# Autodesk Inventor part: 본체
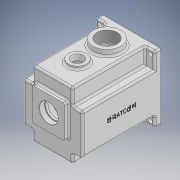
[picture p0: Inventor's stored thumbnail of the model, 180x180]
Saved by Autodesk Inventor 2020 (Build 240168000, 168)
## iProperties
Created: 2022-01
Part Number: 본체
Material: 일반
Document SubType Name: Modeling
Designer: user
Density: 1 g/cm^3
Appearance: 기본값
Mass: 519.717 g
Surface Area: 1171.01 cm^2
Volume: 519.717 cm^3
Author: user
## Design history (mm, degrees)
sketch "스케치1"
  geometry: L1 (-49, -55)-(49, -55); L2 (49, -55)-(49, 55); L3 (49, 55)-(-49, 55); L4 (-49, 55)-(-49, -55); L5 (-49, -55)-(49, 55); L6 (49, -55)-(-49, 55); 1 further point
  constraints: 12 end point, 2 midpoint, 2 parallel, 1 horizontal, 1 perpendicular
  dimensions: "d0" = 98 distance of L3.end L2.end; "d1" = 110 distance of L2.end L1.end
extrude "돌출1" new body sketch "스케치1" stored distance "d2" = 130; taper "d3" = 0 deg
sketch "스케치2"
  geometry: L1 (49, -55)-(49, 55) reference; L2 (49, 55)-(33, 55); L3 (33, 55)-(33, 28); L4 (33, 28)-(49, 28); L5 (49, 28)-(49, 55); L6 (49, -55)-(33, -55); L7 (33, -55)-(33, -38); L8 (33, -38)-(49, -38); L9 (49, -38)-(49, -55); L10 (49, 55)-(-49, 55) reference; L11 (-49, 55)-(-33, 55); L12 (-33, 55)-(-33, 28); L13 (-33, 28)-(-49, 28); L14 (-49, 28)-(-49, 55); L15 (-49, 55)-(-49, -55) reference; L16 (-49, -55)-(-33, -55); L17 (-33, -55)-(-33, -38); L18 (-33, -38)-(-49, -38); L19 (-49, -38)-(-49, -55); 5 further points
  constraints: 32 end point, 8 parallel, 4 horizontal, 4 perpendicular
  dimensions: "d4" = 27 distance of L3.end L2.end; "d5" = 16 distance of L1.end L2.end; "d6" = 17 distance of L6.end L7.end; "d7" = 16 distance of L7.end L8.end; "d8" = 16 distance of L12.end L13.end; "d9" = 27 distance of L11.end L12.end; "d10" = 16 distance of L18.end L17.end; "d11" = 17 distance of L17.end L16.end
extrude "돌출2" cut sketch "스케치2" distance "d12" = 120; taper "d13" = 0 deg
node "작업 평면1"
sketch "스케치4"
  geometry: L1 (0, 0)-(98, 0) reference; L2 (49, 0)-(49, -40); L3 (49, -40)-(49, -89); C1 r 23 at (49, -40); C2 r 15 at (49, -89); 1 further point
  constraints: 4 end point, 2 centre point, 2 coincident, 2 vertical, 1 midpoint
  dimensions: "d19" = 40 distance of L2.start L2.end; "d20" = 46 diameter of C1; "d21" = 49 distance of L3.start L3.end; "d22" = 30 diameter of C2
extrude "돌출4" join sketch "스케치4" distance "d23" = 10; taper "d24" = 0 deg
extrude "돌출5" join sketch "스케치4" distance "d25" = 5; taper "d26" = 0 deg
sketch "스케치6"
  geometry: L1 (0, 0)-(0, 6); L2 (-27, -21)-(27, -21); L3 (27, -21)-(27, 33); L4 (27, 33)-(-27, 33); L5 (-27, 33)-(-27, -21); L6 (-27, -21)-(27, 33); L7 (27, -21)-(-27, 33); L8 (-33, -55)-(33, -55) reference; C1 r 16 at (0, 6)
  constraints: 14 end point, 2 midpoint, 2 parallel, 1 centre point, 1 coincident, 1 horizontal, 1 perpendicular, 1 vertical
  dimensions: "d39" = 32 diameter of C1; "d40" = 54 distance of L4.end L3.end; "d41" = 54 distance of L3.end L2.end; "d178" = 61 distance from line of L1.end L8
extrude "돌출8" join sketch "스케치6" distance "d42" = 7; taper "d43" = 0 deg
sketch "스케치7"
  geometry: L1 (27, 33)-(-27, 33) reference; L2 (0, 33)-(0, 6); C1 r 16 at (0, 6); 1 further point
  constraints: 2 end point, 1 centre point, 1 coincident, 1 midpoint, 1 vertical
  dimensions: "d44" = 27 distance of L2.start L2.end; "d45" = 32 diameter of C1
extrude "돌출9" cut sketch "스케치7" distance "d46" = 0.8; taper "d47" = -30 deg
sketch "스케치8"
  geometry: C1 r 15.538 at (0, 0) reference; 1 further point
extrude "돌출10" cut sketch "스케치8" distance "d48" = 8.3; taper "d49" = 0 deg
sketch "스케치16"
  geometry: C1 r 23 at (0, 0) reference; 2 further points
  constraints: 1 coincident
hole "구멍3" sketch "스케치16" at (0, 0) diameter "d76" = 33.376; stored, may be unused: countersink angle "d80" = 90 deg, drill point angle "d82" = 0 deg; dims "d77" = 19, "d78" = 22, "d79" = 7, "d81" = 22
sketch "스케치18"
  geometry: C1 r 15 at (0, 0) reference; 2 further points
  constraints: 1 coincident
hole "구멍4" sketch "스케치18" at (0, 0) diameter "d87" = 20; stored, may be unused: countersink angle "d91" = 90 deg, drill point angle "d93" = 0 deg; dims "d88" = 19, "d89" = 22, "d90" = 7, "d92" = 20
sketch "스케치19"
  geometry: L1 (33, 55)-(49, 55) reference; L2 (49, 55)-(49, 28) reference; L3 (0, 0)-(0, 87.933); L4 (0, 0)-(72.07, 0); C1 r 3.5 at (42, 48); C2 r 3.5 at (-42, 48); C3 r 3.5 at (-42, -48); C4 r 3.5 at (42, -48)
  constraints: 4 centre point, 4 end point, 3 symmetric about line, 1 horizontal, 1 vertical, 3 other
  dimensions: "d94" = 7 diameter of C1; "d95" = 7 distance from line of L1 C1.centre; "d96" = 7 distance from line of L2 C1.centre
extrude "돌출14" cut sketch "스케치19" distance "d97" = 10; taper "d98" = 0 deg
sketch "스케치21"
  geometry: L1 (33, -55)-(-33, -55) reference; L2 (0, -55)-(0, -5); L3 (0, -5)-(0, 45); L4 (0, 45)-(23, 45); L5 (0, 45)-(-23, 45); L6 (-23, 45)-(-23, 22.354); L7 (23, 45)-(23, 18.054); C1 r 42 at (0, -5); 3 further points
  constraints: 12 end point, 4 vertical, 2 horizontal, 1 centre point, 1 coincident, 1 midpoint
  dimensions: "d102" = 50 distance of L2.start L2.end; "d103" = 84 diameter of C1; "d104" = 50 distance of L3.start L3.end; "d105" = 23 distance of L3.end L4.end; "d106" = 23 distance of L3.end L5.end
extrude "돌출15" cut sketch "스케치21" distance "d107" = 121; taper "d108" = 0 deg
sketch "스케치22"
  geometry: L1 (0, 0)-(0, 6); L2 (0, 0)-(0, -25); C1 r 16 at (0, 6) reference; C2 r 21 at (0, 6); C3 r 15 at (0, -25); 2 further points
  constraints: 4 end point, 2 centre point, 2 coincident, 2 vertical
  dimensions: "d109" = 6 distance of L1.start L1.end (derived); "d110" = 42 diameter of C2; "d111" = 25 distance of L1.start L2.end; "d112" = 30 diameter of C3
extrude "돌출16" join sketch "스케치22" distance "d113" = 7; taper "d114" = 0 deg
sketch "스케치23"
  geometry: A1 r 15 centre (0, -25) between (-8.978, -12.984) and (8.978, -12.984) reference; 2 further points
  constraints: 1 coincident
hole "구멍5" sketch "스케치23" at (0, -25) diameter "d115" = 19; stored, may be unused: countersink angle "d119" = 90 deg, drill point angle "d121" = 0 deg; dims "d116" = 19, "d117" = 22, "d118" = 7, "d120" = 10
sketch "스케치24"
  geometry: A1 r 21 centre (0, 6) between (8.978, -12.984) and (-8.978, -12.984) reference; 2 further points
  constraints: 1 coincident
hole "구멍6" sketch "스케치24" at (0, 6) diameter "d122" = 35; stored, may be unused: countersink angle "d126" = 90 deg, drill point angle "d128" = 0 deg; dims "d123" = 19, "d124" = 22, "d125" = 7, "d127" = 10
sketch "스케치25"
  geometry: C1 r 15.538 at (0, 0) reference; 2 further points
  constraints: 1 coincident
hole "구멍7" sketch "스케치25" at (0, 0) diameter "d129" = 28; stored, may be unused: countersink angle "d133" = 90 deg, drill point angle "d135" = 0 deg; dims "d130" = 19, "d131" = 22, "d132" = 7, "d134" = 10
sketch "스케치26"
  geometry: C1 r 10 at (23, 89) reference; C2 r 15 at (23, 89); 1 further point
  constraints: 1 centre point, 1 coincident
  dimensions: "d136" = 30 diameter of C2
extrude "돌출17" cut sketch "스케치26" distance "d137" = 5; taper "d138" = 0 deg
sketch "스케치27"
  geometry: L1 (23, 45)-(23, 30.143) reference; L2 (-23, 45)-(23, 45) reference; L3 (-23, 30.143)-(-23, 45) reference; L4 (-26, 31.729)-(-26, 48); L5 (-26, 48)-(26, 48); L6 (26, 48)-(26, 31.729); A1 r 42 centre (0, -5) between (-23, 30.143) and (23, 30.143) reference; A2 r 45 centre (0, -5) between (-26, 31.729) and (26, 31.729); 1 further point
  constraints: 6 end point, 2 point on circle, 1 centre point, 3 other
  dimensions: "d139" = 3 distance between parallel lines of L1 L6
extrude "돌출18" cut sketch "스케치27" distance "d140" = 9; taper "d141" = 0 deg
sketch "스케치29" dims "d149" = 8, "d150" = 8
  geometry: L1 (0, -47)-(0, -5); L2 (35.778, -1.006)-(63.216, -1.006); L3 (35.521, -10.852)-(64.123, -10.852); L4 (-35.778, -1.006)-(-61.244, -1.006); L5 (-35.777, -9)-(-63.569, -9); A1 r 42 centre (0, -5) between (-23, 30.143) and (23, 30.143) reference; A2 r 36 centre (0, -5) between (-36, -5) and (36, -5); 4 further points
  constraints: 10 end point, 7 point on circle, 5 horizontal, 1 centre point, 1 coincident, 1 horizontal alignment, 1 vertical, 1 vertical alignment, 6 other
  dimensions: "d147" = 42 distance of L1.start L1.end; "d148" = 72 diameter of A2
fillet "모깎기1" dims "d151" = 3
fillet "모깎기2" dims "d152" = 3
fillet "모깎기3" dims "d153" = 3
sketch "스케치30"
  geometry: L1 (-130, 107)-(-130, 86) reference; L2 (-10, 83)-(-127, 83) reference; 3 further points
  constraints: 1 other
  dimensions: "d154" = 65 distance from line of L1 point (-65, 50); "d157" = 33 distance from line of point (-65, 50) L2
extrude "돌출20" join sketch "스케치29" distance "d155" = 112; taper "d156" = 0 deg
feature "엠보싱1" dims "d158" = 0.5, "d159" = 0
fillet "모깎기4" dims "d160" = 3
fillet "모깎기6" dims "d162" = 0.3
sketch "스케치31"
  geometry: A1 r 4 centre (-36, -5) between (-36, -9) and (-35.778, -1.006) reference; A2 r 4 centre (36, -5) between (35.778, -1.006) and (36, -9) reference; 3 further points
  constraints: 2 coincident
hole "구멍8" sketch "스케치31" at (-36, -5), (36, -5) diameter "d163" = 3.242; stored, may be unused: countersink angle "d167" = 90 deg, drill point angle "d169" = 118 deg; dims "d164" = 7, "d165" = 22, "d166" = 7, "d168" = 9
fillet "모깎기8" dims "d171" = 6
fillet "모깎기9" dims "d172" = 3
fillet "모깎기10" dims "d173" = 3
fillet "모깎기11" dims "d174" = 3
chamfer "모따기1" distance "d175" = 1; stored, may be unused: second distance "d176" = 2, angle "d177" = 45 deg
sketch "스케치32"
  geometry: 1 further point
fillet "모깎기12" dims "d179" = 3
fillet "모깎기13" dims "d180" = 3
fillet "모깎기14" dims "d181" = 3
node "솔리드1"
mirror "미러1"
feature "A9D066F2-1C7D-4E18-AEED-F7BC21143FA4" dims "d87" = 20, "d88" = 19, "d89" = 22, "d90" = 7, "d91" = 90 deg, "d92" = 20, "d93" = 0
other parameters: "d14" = 7
